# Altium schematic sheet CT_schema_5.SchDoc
size 400 x 230 mm
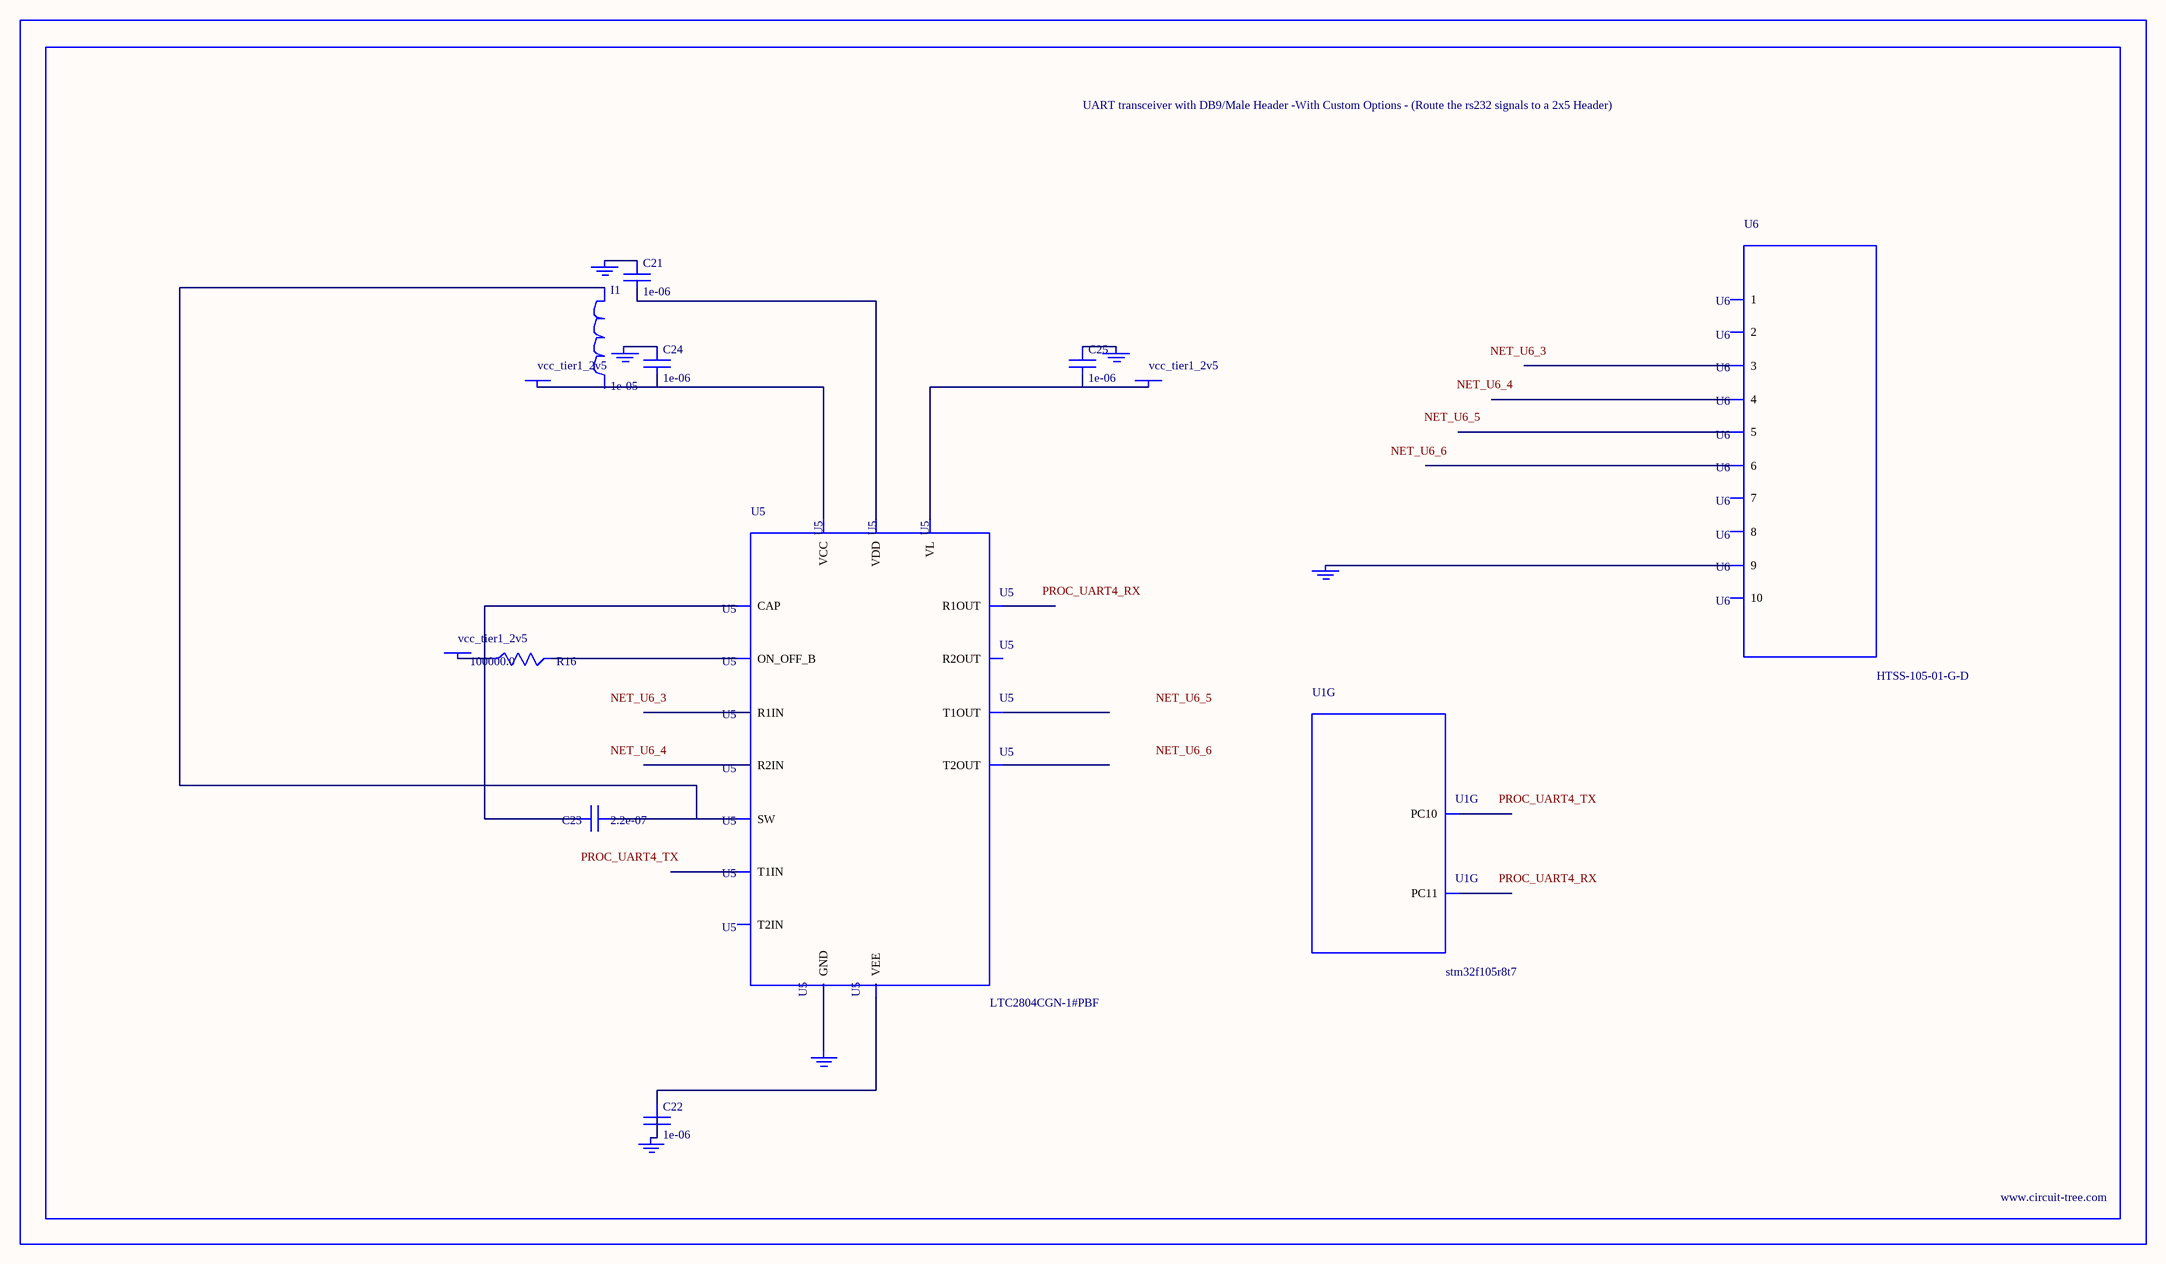
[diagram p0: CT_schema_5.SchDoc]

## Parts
BORDER4  (no value)
C21  1e-06  [C0603]
C22  1e-06  [C0603]
C23  2.2e-07  [C0603]
C24  1e-06  [C0603]
C25  1e-06  [C0603]
GND_INSTANCE_4_0  (no value)
GND_INSTANCE_4_1  (no value)
GND_INSTANCE_4_2  (no value)
GND_INSTANCE_4_3  (no value)
GND_INSTANCE_4_4  (no value)
GND_INSTANCE_4_5  (no value)
I1  1e-05  [L1210]
POWER_INSTANCE_4_0  vcc_tier1_2v5
POWER_INSTANCE_4_1  vcc_tier1_2v5
POWER_INSTANCE_4_2  vcc_tier1_2v5
R16  100000.0  [R0603]
U1  stm32f105r8t7  [LQFP64]  (part G of 7)
U5  LTC2804CGN-1#PBF  [SSOP-16]
U6  HTSS-105-01-G-D  [HTSS-105-01-G-D]

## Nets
NetC21_1: C21.1 GND_INSTANCE_4_1.0(GND)
NetC21_2: C21.2 U5.6(VDD)
NetC22_1: C22.1 U5.9(VEE)
NetC22_2: C22.2 GND_INSTANCE_4_2.0(GND)
NetC23_1: C23.1 I1.1 U5.7(SW)
NetC23_2: C23.2 U5.10(CAP)
NetC24_1: C24.1 GND_INSTANCE_4_0.0(GND)
NetC24_2: C24.2 POWER_INSTANCE_4_0.0(PWR) U5.5(VCC)
NetC25_1: C25.1 GND_INSTANCE_4_3.0(GND)
NetC25_2: C25.2 POWER_INSTANCE_4_2.0(PWR) U5.12(VL)
NetGND_INSTANCE_4_4_0: GND_INSTANCE_4_4.0(GND) U5.8(GND)
NetGND_INSTANCE_4_5_0: GND_INSTANCE_4_5.0(GND) U6.9
NetPOWER_INSTANCE_4_1_0: POWER_INSTANCE_4_1.0(PWR) R16.1
NetR16_2: R16.2 U5.11(ON_OFF_B)

Not connected (* = marked no-connect by the designer): I1 2; U1 51(PC10) 52(PC11); U5 1(R1IN) 2(R2IN) 3(T1OUT) 4(T2OUT) 13(T2IN) 14(T1IN) 15(R2OUT) 16(R1OUT); U6 1 2 3 4 5 6 7 8 10

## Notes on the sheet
- Labels drawn without touching a wire or pin: NET_U6_3, NET_U6_4, NET_U6_5, NET_U6_6, PROC_UART4_RX, PROC_UART4_TX

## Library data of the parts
BORDER4 = BORDER_PAGE4
C21 C22 C24 C25 = C0603C105K3RACTU
C23 = C0603C224K3RAC
GND_INSTANCE_4_0-GND_INSTANCE_4_5 = GND
I1 = CBC3225T100MR
POWER_INSTANCE_4_0-POWER_INSTANCE_4_2 = PWR
R16 = RC0603JR-07100KL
